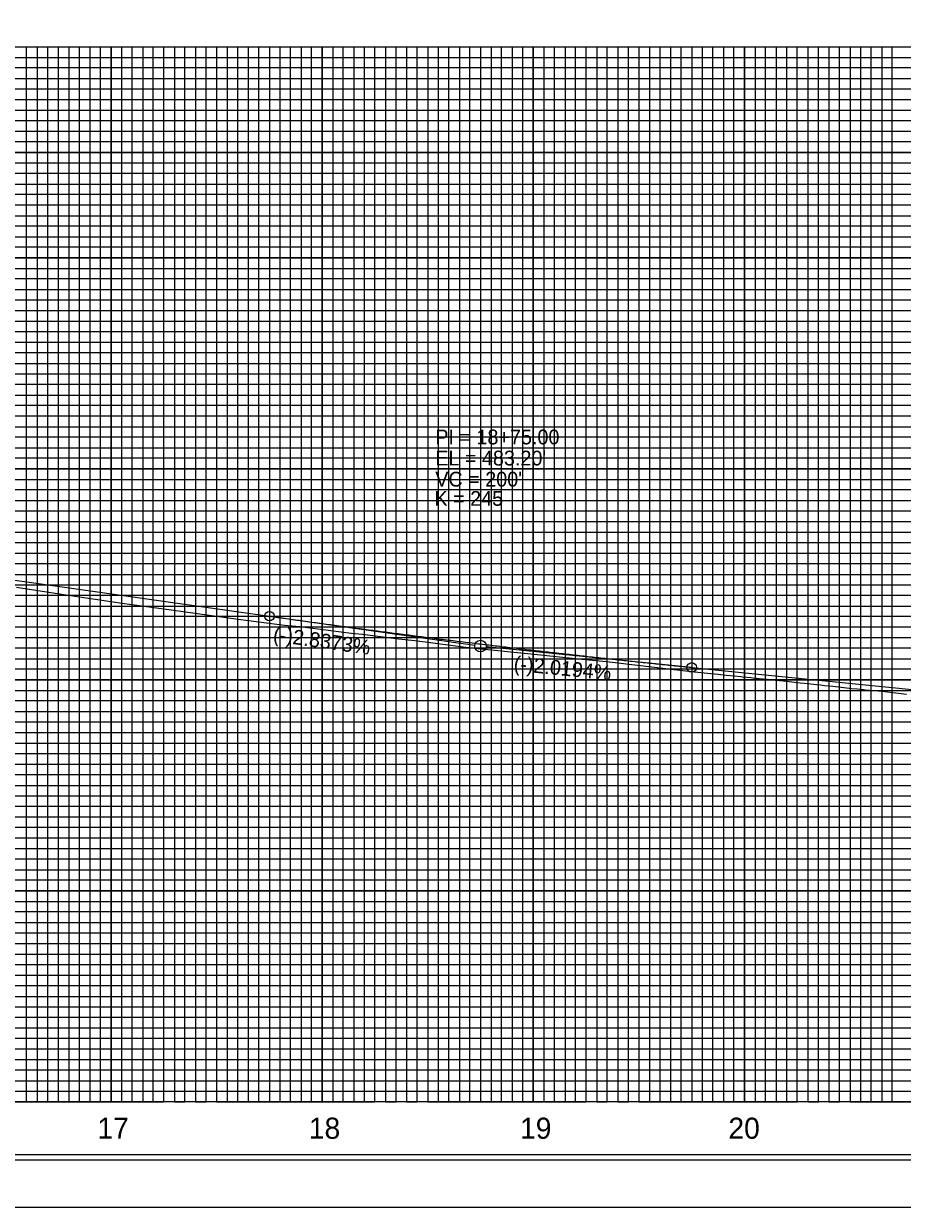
# Model space of a CAD drawing. Extents: x 571503 to 593215, y -77195 to -51828.
# Drawn here: x 582756 to 583172, y -72483 to -71922 of the extents above; entities that cross this region are included whole.
import ezdxf

# ---------------------------------------------------------------- set-up
doc = ezdxf.new("R2010")
doc.units = 0
for name, color, linetype in [('Exist Vertical Profile Ground Line', 7, 'Continuous'), ('Exist Vertical Profile Horizontal Axis Label Major', 7, 'Continuous'), ('Prop Vertical Profile Curve Label', 7, 'Continuous'), ('Prop Vertical Profile Grade', 7, 'Continuous'), ('Prop Vertical Profile Grade Label', 7, 'Continuous'), ('Prop VPI Label', 7, 'Continuous'), ('Sheet Cutting Line CELL', 7, 'Continuous'), ('Sheet DOT Grid CELL', 7, 'Continuous'), ('Sheet Layout Profile Border Port 2', 7, 'Continuous'), ('Sheet Plot Border Inside CELL', 7, 'Continuous'), ('Sheet Plot Border Outside CELL', 7, 'Continuous'), ('Sheet Profile CELL', 7, 'Continuous'), ('Sheet Profile Grid Major CELL', 7, 'Continuous'), ('Sheet Profile Grid Middle CELL', 7, 'Continuous'), ('Sheet Profile Grid Minor CELL', 7, 'Continuous')]:
    doc.layers.add(name, color=color, linetype=linetype)

msp = doc.modelspace()

# ---------------------------------------------------------------- linework, layer by layer
at = {"layer": 'Exist Vertical Profile Ground Line'}
msp.add_lwpolyline([(582752.17, -72188.99), (582770.56, -72191.74), (582776.69, -72192.68), (582802.3, -72196.51), (582806.76, -72197.2), (582825.52, -72199.69), (582832.17, -72200.68), (582857.26, -72204.02), (582862.13, -72204.75), (582879.15, -72206.89), (582886.37, -72207.62), (582910.87, -72210.69), (582916.12, -72211.22), (582933.1, -72213.39), (582940.81, -72214.22), (582965, -72217.3), (582970.84, -72217.94), (582987.9, -72219.75), (582995.82, -72220.54), (583019.88, -72223.08), (583026.53, -72223.69), (583033.09, -72224.35), (583049, -72226.22), (583071.7, -72228.87), (583081.09, -72229.81), (583084.45, -72230.16), (583088.34, -72230.56), (583092.22, -72230.97), (583095.24, -72231.28), (583096.1, -72231.37), (583099.99, -72231.76), (583101.09, -72231.87), (583103.87, -72232.16), (583107.76, -72232.55), (583111.19, -72232.9), (583111.64, -72232.95), (583115.53, -72233.36), (583119.41, -72233.78), (583123.29, -72234.19), (583127.18, -72234.61), (583131.06, -72235.03), (583133.05, -72235.24), (583134.95, -72235.45), (583138.83, -72235.88), (583142.72, -72236.32), (583146.6, -72236.75), (583147.73, -72236.88), (583150.48, -72237.14), (583153.43, -72237.42), (583154.37, -72237.51), (583158.25, -72237.88), (583162.14, -72238.26), (583162.19, -72238.26), (583166.02, -72238.7), (583169.91, -72239.15), (583173.79, -72239.6)], dxfattribs=at)
at = {"layer": 'Prop Vertical Profile Curve Label'}
for centre in [(582871.98, -72202.66), (583071.98, -72226.95)]:
    msp.add_circle(centre, 2.25, dxfattribs=at)
at = {"layer": 'Prop Vertical Profile Grade'}
for p, q in [((582746.98, -72184.93), (582871.98, -72202.66)), ((583071.98, -72226.95), (583231.98, -72243.1))]:
    msp.add_line(p, q, dxfattribs=at)
msp.add_spline([(582871.98, -72202.66), (582875.98, -72203.23), (582879.98, -72203.79), (582883.98, -72204.35), (582887.98, -72204.9), (582891.98, -72205.46), (582895.98, -72206.01), (582899.98, -72206.55), (582903.98, -72207.1), (582907.98, -72207.64), (582911.98, -72208.17), (582915.98, -72208.71), (582919.98, -72209.24), (582923.98, -72209.76), (582927.98, -72210.29), (582931.98, -72210.81), (582935.98, -72211.32), (582939.98, -72211.84), (582943.98, -72212.35), (582947.98, -72212.85), (582951.98, -72213.36), (582955.98, -72213.86), (582959.98, -72214.35), (582963.98, -72214.85), (582967.98, -72215.34), (582971.98, -72215.83), (582975.98, -72216.31), (582979.98, -72216.79), (582983.98, -72217.27), (582987.98, -72217.74), (582991.98, -72218.21), (582995.98, -72218.68), (582999.98, -72219.15), (583003.98, -72219.61), (583007.98, -72220.06), (583011.98, -72220.52), (583015.98, -72220.97), (583019.98, -72221.42), (583023.98, -72221.86), (583027.98, -72222.3), (583031.98, -72222.74), (583035.98, -72223.18), (583039.98, -72223.61), (583043.98, -72224.04), (583047.98, -72224.46), (583051.98, -72224.88), (583055.98, -72225.3), (583059.98, -72225.72), (583063.98, -72226.13), (583067.98, -72226.54), (583071.98, -72226.95)], degree=3, dxfattribs=at)
at = {"layer": 'Prop VPI Label'}
for p, q in [((582871.98, -72202.66), (582969.26, -72216.46)), ((583071.98, -72226.95), (582974.72, -72217.12))]:
    msp.add_line(p, q, dxfattribs=at)
msp.add_circle((582971.98, -72216.85), 2.75, dxfattribs=at)
at = {"layer": 'Sheet Cutting Line CELL'}
msp.add_line((582329.98, -72482.85), (584013.98, -72482.85), dxfattribs=at)
at = {"layer": 'Sheet DOT Grid CELL'}
for p, q in [((582496.98, -71932.85), (583996.87, -71932.85)), ((582796.98, -71932.85), (582796.98, -72432.85)), ((582846.98, -71932.85), (582846.98, -72432.85)), ((582896.98, -71932.85), (582896.98, -72432.85)), ((582946.98, -71932.85), (582946.98, -72432.85)), ((582996.98, -71932.85), (582996.98, -72432.85)), ((583046.98, -71932.85), (583046.98, -72432.85)), ((583096.98, -71932.85), (583096.98, -72432.85)), ((583146.98, -71932.85), (583146.98, -72432.85)), ((582496.98, -71982.85), (583996.87, -71982.85)), ((582496.98, -72032.85), (583996.87, -72032.85)), ((582496.98, -72082.85), (583996.87, -72082.85)), ((582496.98, -72132.85), (583996.87, -72132.85)), ((582496.98, -72182.85), (583996.87, -72182.85)), ((582496.98, -72232.85), (583996.87, -72232.85)), ((582496.98, -72282.85), (583996.87, -72282.85)), ((582496.98, -72332.85), (583996.87, -72332.85)), ((582496.98, -72382.85), (583996.87, -72382.85))]:
    msp.add_line(p, q, dxfattribs=at)
at = {"layer": 'Sheet Layout Profile Border Port 2'}
msp.add_lwpolyline([(582546.98, -71932.85), (583946.98, -71932.85), (583946.98, -72432.85), (582546.98, -72432.85)], close=True, dxfattribs=at)
at = {"layer": 'Sheet Plot Border Inside CELL'}
msp.add_lwpolyline([(582342.98, -72460.4), (584009.48, -72460.4), (584009.48, -71405.3), (582342.98, -71405.3)], close=True, dxfattribs=at)
at = {"layer": 'Sheet Plot Border Outside CELL'}
msp.add_lwpolyline([(582329.98, -72482.85), (584013.98, -72482.85), (584013.98, -71382.85), (582329.98, -71382.85)], close=True, dxfattribs=at)
at = {"layer": 'Sheet Profile CELL'}
for p, q in [((582496.98, -71932.85), (583996.98, -71932.85)), ((583996.98, -72432.85), (582496.98, -72432.85)), ((582496.98, -72457.85), (583996.98, -72457.85))]:
    msp.add_line(p, q, dxfattribs=at)
msp.add_lwpolyline([(583996.98, -71407.85), (582496.98, -71407.85), (582496.98, -72457.85), (583996.98, -72457.85)], close=True, dxfattribs=at)
at = {"layer": 'Sheet Profile Grid Major CELL'}
for p, q in [((582996.98, -71932.85), (583046.98, -71932.85)), ((583096.98, -71932.85), (583146.98, -71932.85))]:
    msp.add_line(p, q, dxfattribs=at)
for points in [[(582746.98, -72432.85), (582796.98, -72432.85), (582796.98, -71932.85), (582846.98, -71932.85), (582846.98, -72432.85), (582896.98, -72432.85), (582896.98, -71932.85), (582946.98, -71932.85), (582946.98, -72432.85), (582996.98, -72432.85), (582996.98, -71932.85), (583046.98, -71932.85), (583046.98, -72432.85), (583096.98, -72432.85), (583096.98, -71932.85), (583146.98, -71932.85), (583146.98, -72432.85), (583196.98, -72432.85)], [(583996.98, -71982.85), (582496.98, -71982.85)], [(583996.98, -72032.85), (582496.98, -72032.85), (582496.98, -72082.85), (583996.98, -72082.85)], [(583996.98, -72132.85), (582496.98, -72132.85), (582496.98, -72182.85), (583996.98, -72182.85)], [(583996.98, -72232.85), (582496.98, -72232.85), (582496.98, -72282.85), (583996.98, -72282.85)], [(583996.98, -72332.85), (582496.98, -72332.85), (582496.98, -72332.85), (582496.98, -72382.85), (583996.98, -72382.85)], [(583996.98, -72432.85), (582496.98, -72432.85)]]:
    msp.add_lwpolyline(points, dxfattribs=at)
at = {"layer": 'Sheet Profile Grid Middle CELL'}
for points in [[(582721.98, -71932.85), (582771.98, -71932.85), (582771.98, -72432.85), (582821.98, -72432.85), (582821.98, -71932.85), (582871.98, -71932.85), (582871.98, -72432.85), (582921.98, -72432.85), (582921.98, -71932.85), (582971.98, -71932.85), (582971.98, -72432.85), (583021.98, -72432.85), (583021.98, -71932.85), (583071.98, -71932.85), (583071.98, -72432.85), (583121.98, -72432.85), (583121.98, -72432.85), (583121.98, -71932.85), (583171.98, -71932.85)], [(582496.98, -71957.85), (583996.98, -71957.85)], [(583996.98, -72007.85), (582496.98, -72007.85), (582496.98, -72057.85), (583996.98, -72057.85)], [(583996.98, -72107.85), (582496.98, -72107.85), (582496.98, -72157.85), (583996.98, -72157.85)], [(583996.98, -72207.85), (582496.98, -72207.85), (582496.98, -72257.85), (583996.98, -72257.85)], [(583996.98, -72307.85), (582496.98, -72307.85), (582496.98, -72357.85), (583996.98, -72357.85)], [(583996.98, -72407.85), (582496.98, -72407.85)]]:
    msp.add_lwpolyline(points, dxfattribs=at)
at = {"layer": 'Sheet Profile Grid Minor CELL'}
for p, q in [((582546.98, -71937.85), (583946.98, -71937.85)), ((583946.98, -71942.85), (582546.98, -71942.85)), ((582546.98, -71947.85), (583946.98, -71947.85)), ((583946.98, -71952.85), (582546.98, -71952.85)), ((582546.98, -71962.85), (583946.98, -71962.85)), ((583946.98, -71967.85), (582546.98, -71967.85)), ((582546.98, -71972.85), (583946.98, -71972.85)), ((583946.98, -71977.85), (582546.98, -71977.85)), ((582546.98, -71987.85), (583946.98, -71987.85)), ((583946.98, -71992.85), (582546.98, -71992.85)), ((582546.98, -71997.85), (583946.98, -71997.85)), ((583946.98, -72002.85), (582546.98, -72002.85)), ((582546.98, -72012.85), (583946.98, -72012.85)), ((583946.98, -72017.85), (582546.98, -72017.85)), ((582546.98, -72022.85), (583946.98, -72022.85)), ((583946.98, -72027.85), (582546.98, -72027.85)), ((582546.98, -72037.85), (583946.98, -72037.85)), ((583946.98, -72042.85), (582546.98, -72042.85)), ((582546.98, -72047.85), (583946.98, -72047.85)), ((583946.98, -72052.85), (582546.98, -72052.85)), ((582546.98, -72062.85), (583946.98, -72062.85)), ((583946.98, -72067.85), (582546.98, -72067.85)), ((582546.98, -72072.85), (583946.98, -72072.85)), ((583946.98, -72077.85), (582546.98, -72077.85)), ((582546.98, -72087.85), (583946.98, -72087.85)), ((583946.98, -72092.85), (582546.98, -72092.85)), ((582546.98, -72097.85), (583946.98, -72097.85)), ((583946.98, -72102.85), (582546.98, -72102.85)), ((582546.98, -72112.85), (583946.98, -72112.85)), ((583946.98, -72117.85), (582546.98, -72117.85)), ((582546.98, -72122.85), (583946.98, -72122.85)), ((583946.98, -72127.85), (582546.98, -72127.7)), ((582546.98, -72137.85), (583946.98, -72137.85)), ((583946.98, -72142.85), (582546.98, -72142.85)), ((582546.98, -72147.85), (583946.98, -72147.85)), ((583946.98, -72152.85), (582546.98, -72152.85)), ((582546.98, -72162.85), (583946.98, -72162.85)), ((583946.98, -72167.85), (582546.98, -72167.85)), ((582546.98, -72172.85), (583946.98, -72172.85)), ((583946.98, -72177.85), (582546.98, -72177.85)), ((582546.98, -72187.85), (583946.98, -72187.85)), ((583946.98, -72192.85), (582546.98, -72192.85)), ((582546.98, -72197.85), (583946.98, -72197.85)), ((583946.98, -72202.85), (582546.98, -72202.85)), ((582546.98, -72212.85), (583946.98, -72212.85)), ((583946.98, -72217.85), (582546.98, -72217.85)), ((582546.98, -72222.85), (583946.98, -72222.85)), ((583946.98, -72227.85), (582546.98, -72227.85)), ((582546.98, -72237.85), (583946.98, -72237.85)), ((583946.98, -72242.85), (582546.98, -72242.85)), ((582546.98, -72247.85), (583946.98, -72247.85)), ((583946.98, -72252.85), (582546.98, -72252.85)), ((582546.98, -72262.85), (583946.98, -72262.85)), ((583946.98, -72267.85), (582546.98, -72267.85)), ((582546.98, -72272.85), (583946.98, -72272.85)), ((583946.98, -72277.85), (582546.98, -72277.85)), ((582546.98, -72287.85), (583946.98, -72287.85)), ((583946.98, -72292.85), (582546.98, -72292.85)), ((582546.98, -72297.85), (583946.98, -72297.85)), ((583946.98, -72302.85), (582546.98, -72302.85)), ((582546.98, -72312.85), (583946.98, -72312.85)), ((583946.98, -72317.85), (582546.98, -72317.85)), ((582546.98, -72322.85), (583946.98, -72322.85)), ((583946.98, -72327.85), (582546.98, -72327.85)), ((582546.98, -72337.85), (583946.98, -72337.85)), ((583946.98, -72342.85), (582546.98, -72342.85)), ((582546.98, -72347.85), (583946.98, -72347.85)), ((583946.98, -72352.85), (582546.98, -72352.85)), ((582546.98, -72362.85), (583946.98, -72362.85)), ((583946.98, -72367.85), (582546.98, -72367.85)), ((582546.98, -72372.85), (583946.98, -72372.85)), ((583946.98, -72377.85), (582546.98, -72377.85)), ((582546.98, -72387.85), (583946.98, -72387.85)), ((583946.98, -72392.85), (582546.98, -72392.85)), ((582546.98, -72397.85), (583946.98, -72397.85)), ((583946.98, -72402.85), (582546.98, -72402.85)), ((582546.98, -72412.85), (583946.98, -72412.85)), ((583946.98, -72417.85), (582546.98, -72417.85)), ((582546.98, -72422.85), (583946.98, -72422.85)), ((582546.98, -72427.85), (583946.98, -72427.85))]:
    msp.add_line(p, q, dxfattribs=at)
for points in [[(582751.98, -72432.85), (582756.98, -72432.85), (582756.98, -71932.85), (582761.98, -71932.85), (582761.98, -72432.85)], [(582761.98, -72432.85), (582766.98, -72432.85), (582766.98, -71932.85), (582776.98, -71932.85), (582776.98, -72432.85), (582781.98, -72432.85), (582781.98, -71932.85), (582786.98, -71932.85), (582786.98, -72432.85), (582791.98, -72432.85), (582791.98, -71932.85), (582801.98, -71932.85), (582801.98, -72432.85), (582806.98, -72432.85), (582806.98, -71932.85), (582811.98, -71932.85), (582811.98, -72432.85), (582816.98, -72432.85), (582816.98, -71932.85), (582826.98, -71932.85), (582826.98, -72432.85), (582831.98, -72432.85), (582831.98, -71932.85), (582836.98, -71932.85), (582836.98, -72432.85), (582841.98, -72432.85), (582841.98, -71932.85), (582851.98, -71932.85), (582851.98, -72432.85), (582856.98, -72432.85), (582856.98, -71932.85), (582861.98, -71932.85), (582861.98, -72432.85), (582866.98, -72432.85), (582866.98, -71932.85), (582876.98, -71932.85), (582876.98, -72432.85), (582881.98, -72432.85), (582881.98, -71932.85), (582886.98, -71932.85), (582886.98, -72432.85), (582891.98, -72432.85), (582891.98, -71932.85), (582901.98, -71932.85), (582901.98, -72432.85), (582906.98, -72432.85), (582906.98, -71932.85), (582911.98, -71932.85), (582911.98, -72432.85), (582916.98, -72432.85), (582916.98, -71932.85), (582926.98, -71932.85), (582926.98, -72432.85), (582931.98, -72432.85), (582931.98, -71932.85), (582936.98, -71932.85), (582936.98, -72432.85), (582941.98, -72432.85), (582941.98, -71932.85), (582951.98, -71932.85), (582951.98, -72432.85), (582956.98, -72432.85), (582956.98, -71932.85), (582961.98, -71932.85), (582961.98, -72432.85), (582966.98, -72432.85), (582966.98, -71932.85), (582976.98, -71932.85), (582976.98, -72432.85), (582981.98, -72432.85), (582981.98, -71932.85), (582986.98, -71932.85), (582986.98, -72432.85), (582991.98, -72432.85), (582991.98, -71932.85), (583001.98, -71932.85), (583001.98, -72432.85), (583006.98, -72432.85), (583006.98, -71932.85), (583011.98, -71932.85), (583011.98, -72432.85), (583016.98, -72432.85), (583016.98, -71932.85), (583026.98, -71932.85), (583026.98, -72432.85), (583031.98, -72432.85), (583031.98, -71932.85), (583036.98, -71932.85), (583036.98, -72432.85), (583041.98, -72432.85), (583041.98, -71932.85), (583051.98, -71932.85), (583051.98, -72432.85), (583056.98, -72432.85), (583056.98, -71932.85), (583061.98, -71932.85), (583061.98, -72432.85), (583066.98, -72432.85), (583066.98, -71932.85), (583076.98, -71932.85)], [(583076.98, -71932.85), (583076.98, -72432.85), (583081.98, -72432.85), (583081.98, -71932.85), (583086.98, -71932.85), (583086.98, -72432.85), (583091.98, -72432.85), (583091.98, -71932.85), (583101.98, -71932.85), (583101.98, -72432.85), (583106.98, -72432.85), (583106.98, -71932.85), (583111.98, -71932.85), (583111.98, -72432.85), (583116.98, -72432.85), (583116.98, -71932.85), (583126.98, -71932.85), (583126.98, -72432.85), (583131.98, -72432.85), (583131.98, -71932.85), (583136.98, -71932.85), (583136.98, -72432.85), (583141.98, -72432.85), (583141.98, -71932.85), (583151.98, -71932.85), (583151.98, -72432.85), (583156.98, -72432.85), (583156.98, -71932.85), (583161.98, -71932.85), (583161.98, -72432.85), (583166.98, -72432.85), (583166.98, -71932.85), (583176.98, -71932.85)]]:
    msp.add_lwpolyline(points, dxfattribs=at)

# ---------------------------------------------------------------- texts
at = {"layer": 'Exist Vertical Profile Horizontal Axis Label Major'}
for s, p in [('17', (582790.52, -72450.35)), ('18', (582890.65, -72450.35)), ('19', (582990.69, -72450.35)), ('20', (583089.37, -72450.35))]:
    msp.add_text(s, height=10, dxfattribs=at).set_placement(p)
at = {"layer": 'Prop Vertical Profile Curve Label'}
for s, p in [("VC = 200'", (582950.53, -72141.24)), ('K = 245', (582950.16, -72150.36))]:
    msp.add_text(s, height=7, dxfattribs=at).set_placement(p)
at = {"layer": 'Prop Vertical Profile Grade Label'}
for s, rotation, p in [('(-)2.8373%', 351.9255, (582873.43, -72214.5)), ('(-)2.0194%', 354.2343, (582987.47, -72228.46))]:
    msp.add_text(s, height=7, rotation=rotation, dxfattribs=at).set_placement(p)
at = {"layer": 'Prop VPI Label'}
for s, p in [('PI = 18+75.00', (582950.53, -72121.24)), ("EL = 483.20'", (582950.53, -72131.24))]:
    msp.add_text(s, height=7, dxfattribs=at).set_placement(p)

doc.saveas('drawing.dxf')
